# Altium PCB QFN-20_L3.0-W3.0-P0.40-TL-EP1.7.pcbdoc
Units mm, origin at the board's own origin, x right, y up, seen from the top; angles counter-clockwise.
Board outline 16.56 x 16.3 mm, 2 copper layers (Top Layer, Bottom Layer), stack 0 mm thick; 1 components, 0 nets, 21 pads, 0 vias.
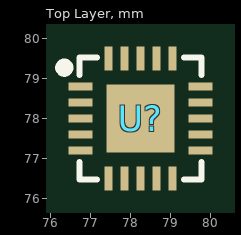
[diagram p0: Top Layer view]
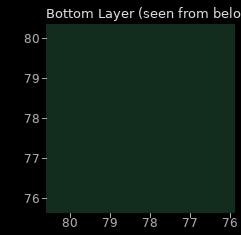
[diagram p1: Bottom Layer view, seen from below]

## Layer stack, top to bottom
Top Layer: signal copper (thickness not stored)
Bottom Layer: signal copper (thickness not stored)

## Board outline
86.405,69.85 69.85,69.85 69.85,86.15 86.405,86.15

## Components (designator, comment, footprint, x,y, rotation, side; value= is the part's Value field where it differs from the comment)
U? "" QFN-20_L3.0-W3.0-P0.40-TL-EP1.7 78.255,78 r0 top

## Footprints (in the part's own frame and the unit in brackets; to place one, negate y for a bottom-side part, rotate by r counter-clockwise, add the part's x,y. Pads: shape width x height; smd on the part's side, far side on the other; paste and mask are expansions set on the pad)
QFN-20_L3.0-W3.0-P0.40-TL-EP1.7 [mm]
  rect 0.6x0.2 smd paste-100 mask+0.051: 1(-1.5,0.8) 2(-1.5,0.4) 3(-1.5,0) 4(-1.5,-0.4) 5(-1.5,-0.8) 11(1.5,-0.8) 12(1.5,-0.4) 13(1.5,0) 14(1.5,0.4) 15(1.5,0.8)
  rect 0.2x0.6 smd paste-100 mask+0.051: 6(-0.8,-1.5) 7(-0.4,-1.5) 8(0,-1.5) 9(0.4,-1.5) 10(0.8,-1.5) 16(0.8,1.5) 17(0.4,1.5) 18(0,1.5) 19(-0.4,1.5) 20(-0.8,1.5)
  rect 1.7x1.7 smd paste-100 mask+0.051: 21(0,0)
  silkscreen extent -2,-1.52 1.52,1.52

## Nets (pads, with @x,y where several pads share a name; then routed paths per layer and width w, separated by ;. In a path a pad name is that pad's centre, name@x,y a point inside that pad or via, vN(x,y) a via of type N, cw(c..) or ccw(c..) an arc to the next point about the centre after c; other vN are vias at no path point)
pads on no net: U?.1 U?.2 U?.3 U?.4 U?.5 U?.6 U?.7 U?.8 U?.9 U?.10 U?.11 U?.12 U?.13 U?.14 U?.15 U?.16 U?.17 U?.18 U?.19 U?.20 U?.21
